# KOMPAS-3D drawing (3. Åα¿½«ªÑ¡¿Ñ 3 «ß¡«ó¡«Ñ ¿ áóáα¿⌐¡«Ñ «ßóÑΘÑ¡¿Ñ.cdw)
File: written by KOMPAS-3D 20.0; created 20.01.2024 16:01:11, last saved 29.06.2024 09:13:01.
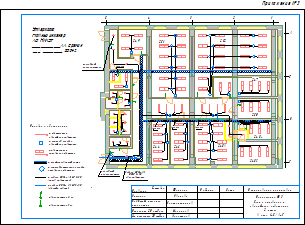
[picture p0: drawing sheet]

Sheet 1: A4, landscape

Document properties: Автор: Пользователь Windows; Организация: НИИЭТ; Полное имя файла: \\Storage\20 Отдел\Мои документы\Крашенинников Е\ТЗ 2й этаж\готово\3. Приложение 3 основное и аварийное освещение.cdw

Title block, sheet 1: scale: 1:1; Количество листов документа: 1; Форматы листов документа: A4

Views: Вид 1, Вид 2
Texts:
  Приложение №3
  Кабель ВВГнг(А)
  FRLS 3х1,5
  авар.освещения
  проходной
  переключатель
  - светильники
  аварийного освещения
  - распред. коробка
  основного освещения
  - перфорированный лоток
  - распределительные коробки
  - кабель ВВГнг (А) LS 3х1,5
  (аварийн. освещ..)
  (основ. освещения)
  - выключатель 2 кл.
  - выключатель 1 кл.
  Утверждаю
  Главный инженер
  АО "НИИЭТ"
  Составил
  Фамилия
  Подпись
  Дата
  Наименование планировки
  Инженер
  Иванова
  Схема основного и
  в осях 1-5/А-Г.
  Ведущий инженер
  энергетик
  Крашенинников
  Начальник 20 отдела
  Меренков
  Зам. начальника 20 отдела
  Хорошилов
  Условные обозначения
  выкл 1кл
  выкл 2кл
  200_ШТРИХ_RGB_255_0_0_SC_1_THICK_0.09
  FP_1_ISO 8
  FP_1_ISO 7
  FP_1_ISO 6
  FP_1_ISO 5
  FP_1_ISO 4
  FP_1_ISO 3
  FP_1_ISO 2
  FP_1_ISO 1
  FP_1_ISO 0
  FP_3_ISO 83
  FP_3_ISO 82
  FP_3_ISO 81
  FP_3_ISO 80
  FP_3_ISO 79
  FP_3_ISO 78
  FP_3_ISO 77
  FP_3_ISO 76
  FP_3_ISO 75
  FP_3_ISO 74
  FP_3_ISO 73
  FP_3_ISO 72
  FP_3_ISO 71
  FP_3_ISO 70
  FP_3_ISO 69
  FP_3_ISO 68
  FP_3_ISO 67
  FP_3_ISO 66
  FP_3_ISO 65
  FP_3_ISO 64
  FP_3_ISO 63
  FP_3_ISO 62
  FP_3_ISO 61
  FP_3_ISO 60
  FP_3_ISO 59
  FP_3_ISO 58
  FP_3_ISO 57
  FP_3_ISO 56
  FP_3_ISO 55
  FP_3_ISO 54
  FP_3_ISO 53
  FP_3_ISO 52
  FP_3_ISO 51
  FP_3_ISO 50
  FP_3_ISO 49
  FP_3_ISO 48
  FP_3_ISO 47
  FP_3_ISO 46
  FP_3_ISO 45
  FP_3_ISO 44
  FP_3_ISO 43
  FP_3_ISO 42
  FP_3_ISO 41
  FP_3_ISO 40
  FP_3_ISO 39
  FP_3_ISO 38
  FP_3_ISO 37
  FP_3_ISO 36
  FP_3_ISO 35
  FP_3_ISO 34
  FP_3_ISO 33
  FP_3_ISO 32
  FP_3_ISO 31
  FP_3_ISO 30
  FP_3_ISO 29
  FP_3_ISO 28
  FP_3_ISO 27
  FP_3_ISO 26
  FP_3_ISO 25
  FP_3_ISO 24
  FP_3_ISO 23
  FP_3_ISO 22
  FP_3_ISO 21
  FP_3_ISO 20
  FP_3_ISO 19
  FP_3_ISO 18
  FP_3_ISO 17
  FP_3_ISO 16
  FP_3_ISO 15
  FP_3_ISO 14
  FP_3_ISO 13
  FP_3_ISO 12
  FP_5_ISO 83
  FP_5_ISO 82
  FP_5_ISO 81
  FP_5_ISO 80
  FP_5_ISO 79
  FP_5_ISO 78
  FP_5_ISO 77
  FP_5_ISO 76
  FP_5_ISO 75
  FP_5_ISO 74
  FP_5_ISO 73
  FP_5_ISO 72
  FP_5_ISO 71
  FP_5_ISO 70
  FP_5_ISO 69
  FP_5_ISO 68
  FP_5_ISO 67
  FP_5_ISO 66
  FP_5_ISO 65
  FP_5_ISO 64
  FP_5_ISO 63
  FP_5_ISO 62
  FP_5_ISO 61
  FP_5_ISO 60
  FP_5_ISO 59
  FP_5_ISO 58
  FP_5_ISO 57
  FP_5_ISO 56
  FP_5_ISO 55
  FP_5_ISO 54
  FP_5_ISO 53
  FP_5_ISO 52
  FP_5_ISO 51
  FP_5_ISO 50
  FP_5_ISO 49
  FP_5_ISO 48
  FP_5_ISO 47
  FP_5_ISO 46
  FP_5_ISO 45
  FP_5_ISO 44
  FP_5_ISO 43
  FP_5_ISO 42
  FP_5_ISO 41
  FP_5_ISO 40
  FP_5_ISO 39
  FP_5_ISO 38
  FP_5_ISO 37
  FP_5_ISO 36
  FP_5_ISO 35
  FP_5_ISO 34
  FP_5_ISO 33
  FP_5_ISO 32
  FP_5_ISO 31
  FP_5_ISO 30
  FP_5_ISO 29
  FP_5_ISO 28
  FP_5_ISO 27
  FP_5_ISO 26
  FP_5_ISO 25
  FP_5_ISO 24
  FP_5_ISO 23
  FP_5_ISO 22
  FP_5_ISO 21
  FP_5_ISO 20
  FP_5_ISO 19
  FP_5_ISO 18
  FP_5_ISO 17
  FP_5_ISO 16
  FP_5_ISO 15
  FP_5_ISO 14
  FP_5_ISO 13
  FP_5_ISO 12
  FP3_1_ISO 0
  FP3_1_ISO 1
  FP3_1_ISO 2
  FP3_1_ISO 3
  FP3_1_ISO 4
  FP3_1_ISO 5
  FP3_1_ISO 6
  FP3_1_ISO 7
  FP3_1_ISO 8
  FP3_1_ISO 9
  FP3_1_ISO 10
  FP3_1_ISO 11
  FP3_1_ISO 12
  FP3_1_ISO 13
  FP3_1_ISO 14
  FP3_1_ISO 15
  FP3_2_ISO 0
  FP3_2_ISO 1
  FP3_2_ISO 2
  FP3_2_ISO 3
  FP3_2_ISO 4
  FP3_2_ISO 5
  FP3_2_ISO 6
  FP3_2_ISO 7
  FP3_2_ISO 8
  FP3_2_ISO 9
  FP3_2_ISO 10
  FP3_2_ISO 11
  FP3_2_ISO 12
  FP3_2_ISO 13
  FP3_2_ISO 14
  FP3_2_ISO 15
  FP3_3_ISO 0
  FP3_3_ISO 1
  FP3_3_ISO 2
  FP3_3_ISO 3
  FP3_3_ISO 4
  FP3_3_ISO 5
  FP3_3_ISO 6
  FP3_3_ISO 7
  FP3_3_ISO 8
  FP3_3_ISO 9
  FP3_3_ISO 10
  FP3_3_ISO 11
  FP3_3_ISO 12
  FP3_3_ISO 13
  FP3_3_ISO 14
  FP3_3_ISO 15
  FP3_4_ISO 0
  FP3_4_ISO 1
  FP3_4_ISO 2
  FP3_4_ISO 3
  FP3_4_ISO 4
  FP3_4_ISO 5
  FP3_4_ISO 6
  FP3_4_ISO 7
  FP3_4_ISO 8
  FP3_4_ISO 9
  FP3_4_ISO 10
  FP3_4_ISO 11
  FP3_4_ISO 12
  FP3_4_ISO 13
  FP3_4_ISO 14
  FP3_4_ISO 15
  FP3_5_ISO 0
  FP3_5_ISO 1
  FP3_5_ISO 2
  FP3_5_ISO 3
  FP3_5_ISO 4
  FP3_5_ISO 5
  FP3_5_ISO 6
  FP3_5_ISO 7
  FP3_5_ISO 8
  FP3_5_ISO 9
  FP3_5_ISO 10
  FP3_5_ISO 11
  FP3_5_ISO 12
  FP3_5_ISO 13
  FP3_5_ISO 14
  FP3_5_ISO 15
  FP3_6_ISO 0
  FP3_6_ISO 1
  FP3_6_ISO 2
  FP3_6_ISO 3
  FP3_6_ISO 4
  FP3_6_ISO 5
  FP3_6_ISO 6
  FP3_6_ISO 7
  FP3_6_ISO 8
  FP3_6_ISO 9
  FP3_6_ISO 10
  FP3_6_ISO 11
  FP3_6_ISO 12
  FP3_6_ISO 13
  FP3_6_ISO 14
  FP3_6_ISO 15
  FP3_7_ISO 0
  FP3_7_ISO 1
  FP3_7_ISO 2
  FP3_7_ISO 3
  FP3_7_ISO 4
  FP3_7_ISO 5
  FP3_7_ISO 6
  FP3_7_ISO 7
  FP3_7_ISO 8
  FP3_7_ISO 9
  FP3_7_ISO 10
  FP3_7_ISO 11
  FP3_7_ISO 12
  FP3_7_ISO 13
  FP3_7_ISO 14
  FP3_7_ISO 15
  FP3_8_ISO 0
  FP3_8_ISO 1
  FP3_8_ISO 2
  FP3_8_ISO 3
  FP3_8_ISO 4
  FP3_8_ISO 5
  FP3_8_ISO 6
  FP3_8_ISO 7
  FP3_8_ISO 8
  FP3_8_ISO 9
  FP3_8_ISO 10
  FP3_8_ISO 11
  FP3_8_ISO 12
  FP3_8_ISO 13
  FP3_8_ISO 14
  FP3_8_ISO 15
  FP3_9_ISO 0
  FP3_9_ISO 1
  FP3_9_ISO 2
  FP3_9_ISO 3
  FP3_9_ISO 4
  FP3_9_ISO 5
  FP3_9_ISO 6
  FP3_9_ISO 7
  FP3_9_ISO 8
  FP3_9_ISO 9
  FP3_9_ISO 10
  FP3_9_ISO 11
  FP3_9_ISO 12
  FP3_9_ISO 13
  FP3_9_ISO 14
  FP3_9_ISO 15
  FP3_10_ISO 0
  FP3_10_ISO 1
  FP3_10_ISO 2
  FP3_10_ISO 3
  FP3_10_ISO 4
  FP3_10_ISO 5
  FP3_10_ISO 6
  FP3_10_ISO 7
  FP3_10_ISO 8
  FP3_10_ISO 9
  FP3_10_ISO 10
  FP3_10_ISO 11
  FP3_10_ISO 12
  FP3_10_ISO 13
  FP3_10_ISO 14
  FP3_10_ISO 15
  FP3_11_ISO 0
  FP3_11_ISO 1
  FP3_11_ISO 2
  FP3_11_ISO 3
  FP3_11_ISO 4
  FP3_11_ISO 5
  FP3_11_ISO 6
  FP3_11_ISO 7
  FP3_11_ISO 8
  FP3_11_ISO 9
  FP3_11_ISO 10
  FP3_11_ISO 11
  FP3_11_ISO 12
  FP3_11_ISO 13
  FP3_11_ISO 14
  FP3_11_ISO 15
  FP3_13_ISO 0
  FP3_13_ISO 1
  FP3_13_ISO 2
  FP3_13_ISO 3
  FP3_13_ISO 4
  FP3_13_ISO 5
  FP3_13_ISO 6
  FP3_13_ISO 7
  FP3_13_ISO 8
  FP3_13_ISO 9
  FP3_13_ISO 10
  FP3_13_ISO 11
  FP3_13_ISO 12
  FP3_13_ISO 13
  FP3_13_ISO 14
  FP3_13_ISO 15
  FP3_14_ISO 0
  FP3_14_ISO 1
  FP3_14_ISO 2
  FP3_14_ISO 3
  FP3_14_ISO 4
  FP3_14_ISO 5
  FP3_14_ISO 6
  FP3_14_ISO 7
  FP3_14_ISO 8
  FP3_14_ISO 9
  FP3_14_ISO 10
  FP3_14_ISO 11
  FP3_14_ISO 12
  FP3_14_ISO 13
  FP3_14_ISO 14
  FP3_14_ISO 15
  FP3_15_ISO 0
  FP3_15_ISO 1
  FP3_15_ISO 2
  FP3_15_ISO 3
  FP3_15_ISO 4
  FP3_15_ISO 5
  FP3_15_ISO 6
  FP3_15_ISO 7
  FP3_15_ISO 8
  FP3_15_ISO 9
  FP3_15_ISO 10
  FP3_15_ISO 11
  FP3_15_ISO 12
  FP3_15_ISO 13
  FP3_15_ISO 14
  FP3_15_ISO 15
  FP3_16_ISO 0
  FP3_16_ISO 1
  FP3_16_ISO 2
  FP3_16_ISO 3
  FP3_16_ISO 4
  FP3_16_ISO 5
  FP3_16_ISO 6
  FP3_16_ISO 7
  FP3_16_ISO 8
  FP3_16_ISO 9
  FP3_16_ISO 10
  FP3_16_ISO 11
  FP3_16_ISO 12
  FP3_16_ISO 13
  FP3_16_ISO 14
  FP3_16_ISO 15
  FP3_17_ISO 0
  FP3_17_ISO 1
  FP3_17_ISO 2
  FP3_17_ISO 3
  FP3_17_ISO 4
  FP3_17_ISO 5
  FP3_17_ISO 6
  FP3_17_ISO 7
  FP3_17_ISO 8
  FP3_17_ISO 9
  FP3_17_ISO 10
  FP3_17_ISO 11
  FP3_17_ISO 12
  FP3_17_ISO 13
  FP3_17_ISO 14
  FP3_17_ISO 15
  FP3_19_ISO 0
  FP3_19_ISO 1
  FP3_19_ISO 2
  FP3_19_ISO 3
  FP3_19_ISO 4
  FP3_19_ISO 5
  FP3_19_ISO 6
  FP3_19_ISO 7
  FP3_19_ISO 8
  FP3_19_ISO 9
  FP3_19_ISO 10
  FP3_19_ISO 11
  FP3_19_ISO 12
  FP3_19_ISO 13
  FP3_19_ISO 14
  FP3_19_ISO 15
  FP3_20_ISO 0
  FP3_20_ISO 1
  FP3_20_ISO 2
  FP3_20_ISO 3
  FP3_20_ISO 4
  FP3_20_ISO 5
  FP3_20_ISO 6
  FP3_20_ISO 7
  FP3_20_ISO 8
  FP3_20_ISO 9
  FP3_20_ISO 10
  FP3_20_ISO 11
  FP3_20_ISO 12
  FP3_20_ISO 13
  FP3_20_ISO 14
  FP3_20_ISO 15
  FP3_21_ISO 0
  FP3_21_ISO 1
  FP3_21_ISO 2
  FP3_21_ISO 3
  FP3_21_ISO 4
  FP3_21_ISO 5
  FP3_21_ISO 6
  FP3_21_ISO 7
  FP3_21_ISO 8
  FP3_21_ISO 9
  FP3_21_ISO 10
  FP3_21_ISO 11
  FP3_21_ISO 12
  FP3_21_ISO 13
  FP3_21_ISO 14
  FP3_21_ISO 15
  FP3_22_ISO 0
  FP3_22_ISO 1
  FP3_22_ISO 2
  FP3_22_ISO 3
  FP3_22_ISO 4
  FP3_22_ISO 5
  FP3_22_ISO 6
  FP3_22_ISO 7
  FP3_22_ISO 8
  FP3_22_ISO 9
  FP3_22_ISO 10
  FP3_22_ISO 11
  FP3_22_ISO 12
  FP3_22_ISO 13
  FP3_22_ISO 14
  FP3_22_ISO 15
  FP3_23_ISO 0
  FP3_23_ISO 1
  FP3_23_ISO 2
  FP3_23_ISO 3
  FP3_23_ISO 4
  FP3_23_ISO 5
  FP3_23_ISO 6
  FP3_23_ISO 7
  FP3_23_ISO 8
  FP3_23_ISO 9
  FP3_23_ISO 10
  FP3_23_ISO 11
  FP3_23_ISO 12
  FP3_23_ISO 13
  FP3_23_ISO 14
  FP3_23_ISO 15
  FP3_24_ISO 0
  FP3_24_ISO 1
  FP3_24_ISO 2
  FP3_24_ISO 3
  FP3_24_ISO 4
  FP3_24_ISO 5
  FP3_24_ISO 6
  FP3_24_ISO 7
  FP3_24_ISO 8
  FP3_24_ISO 9
  FP3_24_ISO 10
  FP3_24_ISO 11
  FP3_24_ISO 12
  FP3_24_ISO 13
  FP3_24_ISO 14
  FP3_24_ISO 15
  FP3_25_ISO 0
  FP3_25_ISO 1
  FP3_25_ISO 2
  FP3_25_ISO 3
  FP3_25_ISO 4
  FP3_25_ISO 5
  FP3_25_ISO 6
  FP3_25_ISO 7
  FP3_25_ISO 8
  FP3_25_ISO 9
  FP3_25_ISO 10
  FP3_25_ISO 11
  FP3_25_ISO 12
  FP3_25_ISO 13
  FP3_25_ISO 14
  FP3_25_ISO 15
  FP3_26_ISO 0
  FP3_26_ISO 1
  FP3_26_ISO 2
  FP3_26_ISO 3
  FP3_26_ISO 4
  FP3_26_ISO 5
  FP3_26_ISO 6
  FP3_26_ISO 7
  FP3_26_ISO 8
  FP3_26_ISO 9
  FP3_26_ISO 10
  FP3_26_ISO 11
  FP3_26_ISO 12
  FP3_26_ISO 13
  FP3_26_ISO 14
  FP3_26_ISO 15
  FP3_28_ISO 0
  FP3_28_ISO 1
  FP3_28_ISO 2
  FP3_28_ISO 3
  FP3_28_ISO 4
  FP3_28_ISO 5
  FP3_28_ISO 6
  FP3_28_ISO 7
  FP3_28_ISO 8
  FP3_28_ISO 9
  FP3_28_ISO 10
  FP3_28_ISO 11
  FP3_28_ISO 12
  FP3_28_ISO 13
  FP3_28_ISO 14
  FP3_28_ISO 15
  FP3_29_ISO 0
  FP3_29_ISO 1
  FP3_29_ISO 2
  FP3_29_ISO 3
  FP3_29_ISO 4
  FP3_29_ISO 5
  FP3_29_ISO 6
  FP3_29_ISO 7
  FP3_29_ISO 8
  FP3_29_ISO 9
  FP3_29_ISO 10
  FP3_29_ISO 11
  FP3_29_ISO 12
  FP3_29_ISO 13
  FP3_29_ISO 14
  FP3_29_ISO 15
  FP3_31_ISO 0
  FP3_31_ISO 1
  FP3_31_ISO 2
  FP3_31_ISO 3
  FP3_31_ISO 4
  FP3_31_ISO 5
  FP3_31_ISO 6
  FP3_31_ISO 7
  FP3_31_ISO 8
  FP3_31_ISO 9
  FP3_31_ISO 10
  FP3_31_ISO 11
  FP3_31_ISO 12
  FP3_31_ISO 13
  FP3_31_ISO 14
  FP3_31_ISO 15
  FP3_32_ISO 0
  FP3_32_ISO 1
  FP3_32_ISO 2
  FP3_32_ISO 3
  FP3_32_ISO 4
  FP3_32_ISO 5
  FP3_32_ISO 6
  FP3_32_ISO 7
  FP3_32_ISO 8
  FP3_32_ISO 9
  FP3_32_ISO 10
  FP3_32_ISO 11
  FP3_32_ISO 12
  FP3_32_ISO 13
  FP3_32_ISO 14
  FP3_32_ISO 15
  FP3_33_ISO 0
  FP3_33_ISO 1
  FP3_33_ISO 2
  FP3_33_ISO 3
  FP3_33_ISO 4
  FP3_33_ISO 5
  FP3_33_ISO 6
  FP3_33_ISO 7
  FP3_33_ISO 8
  FP3_33_ISO 9
  FP3_33_ISO 10
  FP3_33_ISO 11
  FP3_33_ISO 12
  FP3_33_ISO 13
  FP3_33_ISO 14
  FP3_33_ISO 15
  FP3_35_ISO 0
  FP3_35_ISO 1
  FP3_35_ISO 2
  FP3_35_ISO 3
  FP3_35_ISO 4
  FP3_35_ISO 5
  FP3_35_ISO 6
  FP3_35_ISO 7
  FP3_35_ISO 8
  FP3_35_ISO 9
  FP3_35_ISO 10
  FP3_35_ISO 11
  FP3_35_ISO 12
  FP3_35_ISO 13
  FP3_35_ISO 14
  FP3_35_ISO 15
  FP3_36_ISO 0
  FP3_36_ISO 1
  FP3_36_ISO 2
  FP3_36_ISO 3
  FP3_36_ISO 4
  FP3_36_ISO 5
  FP3_36_ISO 6
  FP3_36_ISO 7
  FP3_36_ISO 8
  FP3_36_ISO 9
  FP3_36_ISO 10
  FP3_36_ISO 11
  FP3_36_ISO 12
  FP3_36_ISO 13
  FP3_36_ISO 14
  FP3_36_ISO 15
  FP3_37_ISO 0
  FP3_37_ISO 1
  FP3_37_ISO 2
  FP3_37_ISO 3
  FP3_37_ISO 4
  FP3_37_ISO 5
  FP3_37_ISO 6
  FP3_37_ISO 7
  FP3_37_ISO 8
  FP3_37_ISO 9
  FP3_37_ISO 10
  FP3_37_ISO 11
  FP3_37_ISO 12
  FP3_37_ISO 13
  FP3_37_ISO 14
  FP3_37_ISO 15
  FP3_38_ISO 0
  FP3_38_ISO 1
  FP3_38_ISO 2
  FP3_38_ISO 3
  FP3_38_ISO 4
  FP3_38_ISO 5
  FP3_38_ISO 6
  FP3_38_ISO 7
  FP3_38_ISO 8
  FP3_38_ISO 9
  FP3_38_ISO 10
  FP3_38_ISO 11
  FP3_38_ISO 12
  FP3_38_ISO 13
  FP3_38_ISO 14
  FP3_38_ISO 15
  FP3_39_ISO 0
  FP3_39_ISO 1
  FP3_39_ISO 2
  FP3_39_ISO 3
  FP3_39_ISO 4
  FP3_39_ISO 5
  FP3_39_ISO 6
  FP3_39_ISO 7
  FP3_39_ISO 8
  FP3_39_ISO 9
  FP3_39_ISO 10
  FP3_39_ISO 11
  FP3_39_ISO 12
  FP3_39_ISO 13
  FP3_39_ISO 14
  FP3_39_ISO 15
  FP3_40_ISO 0
  FP3_40_ISO 1
  FP3_40_ISO 2
  FP3_40_ISO 3
  FP3_40_ISO 4
  FP3_40_ISO 5
  FP3_40_ISO 6
  FP3_40_ISO 7
  FP3_40_ISO 8
  FP3_40_ISO 9
  FP3_40_ISO 10
  FP3_40_ISO 11
  FP3_40_ISO 12
  FP3_40_ISO 13
  FP3_40_ISO 14
  FP3_40_ISO 15
  FP3_41_ISO 0
  FP3_41_ISO 1
  FP3_41_ISO 2
  FP3_41_ISO 3
  FP3_41_ISO 4
  FP3_41_ISO 5
  FP3_41_ISO 6
  FP3_41_ISO 7
  FP3_41_ISO 8
  FP3_41_ISO 9
  FP3_41_ISO 10
  FP3_41_ISO 11
  FP3_41_ISO 12
  FP3_41_ISO 13
  FP3_41_ISO 14
  FP3_41_ISO 15
  FP3_42_ISO 0
  FP3_42_ISO 1
  FP3_42_ISO 2
  FP3_42_ISO 3
  FP3_42_ISO 4
  FP3_42_ISO 5
  FP3_42_ISO 6
  FP3_42_ISO 7
  FP3_42_ISO 8
  FP3_42_ISO 9
  FP3_42_ISO 10
  FP3_42_ISO 11
  FP3_42_ISO 12
  FP3_42_ISO 13
  FP3_42_ISO 14
  FP3_42_ISO 15
  FP3_44_ISO 0
  FP3_44_ISO 1
  FP3_44_ISO 2
  FP3_44_ISO 3
  FP3_44_ISO 4
  FP3_44_ISO 5
  FP3_44_ISO 6
  FP3_44_ISO 7
  FP3_44_ISO 8
  FP3_44_ISO 9
  FP3_44_ISO 10
  FP3_44_ISO 11
  FP3_44_ISO 12
  FP3_44_ISO 13
  FP3_44_ISO 14
  FP3_44_ISO 15
  FP3_45_ISO 0
  FP3_45_ISO 1
  FP3_45_ISO 2
  FP3_45_ISO 3
  FP3_45_ISO 4
  FP3_45_ISO 5
  FP3_45_ISO 6
  FP3_45_ISO 7
  FP3_45_ISO 8
  FP3_45_ISO 9
  FP3_45_ISO 10
  FP3_45_ISO 11
  FP3_45_ISO 12
  FP3_45_ISO 13
  FP3_45_ISO 14
  FP3_45_ISO 15
  FP3_46_ISO 0
  FP3_46_ISO 1
  FP3_46_ISO 2
  FP3_46_ISO 3
  FP3_46_ISO 4
  FP3_46_ISO 5
  FP3_46_ISO 6
  FP3_46_ISO 7
  FP3_46_ISO 8
  FP3_46_ISO 9
  FP3_46_ISO 10
  FP3_46_ISO 11
  FP3_46_ISO 12
  FP3_46_ISO 13
  FP3_46_ISO 14
  FP3_46_ISO 15
  FP3_47_ISO 0
  FP3_47_ISO 1
  FP3_47_ISO 2
  FP3_47_ISO 3
  FP3_47_ISO 4
  FP3_47_ISO 5
  FP3_47_ISO 6
  FP3_47_ISO 7
  FP3_47_ISO 8
  FP3_47_ISO 9
  FP3_47_ISO 10
  FP3_47_ISO 11
  FP3_47_ISO 12
  FP3_47_ISO 13
  FP3_47_ISO 14
  FP3_47_ISO 15
  FP3_48_ISO 0
  FP3_48_ISO 1
  FP3_48_ISO 2
  FP3_48_ISO 3
  FP3_48_ISO 4
  FP3_48_ISO 5
  FP3_48_ISO 6
  FP3_48_ISO 7
  FP3_48_ISO 8
  FP3_48_ISO 9
  FP3_48_ISO 10
  FP3_48_ISO 11
  FP3_48_ISO 12
  FP3_48_ISO 13
  FP3_48_ISO 14
  FP3_48_ISO 15
  FP3_49_ISO 0
  FP3_49_ISO 1
  FP3_49_ISO 2
  FP3_49_ISO 3
  FP3_49_ISO 4
  FP3_49_ISO 5
  FP3_49_ISO 6
  FP3_49_ISO 7
  FP3_49_ISO 8
  FP3_49_ISO 9
  FP3_49_ISO 10
  FP3_49_ISO 11
  FP3_49_ISO 12
  FP3_49_ISO 13
  FP3_49_ISO 14
  FP3_49_ISO 15
  FP3_50_ISO 0
  FP3_50_ISO 1
  FP3_50_ISO 2
  FP3_50_ISO 3
  FP3_50_ISO 4
  FP3_50_ISO 5
  FP3_50_ISO 6
  FP3_50_ISO 7
  FP3_50_ISO 8
  FP3_50_ISO 9
  FP3_50_ISO 10
  FP3_50_ISO 11
  FP3_50_ISO 12
  FP3_50_ISO 13
  FP3_50_ISO 14
  FP3_50_ISO 15
  FP3_51_ISO 0
  FP3_51_ISO 1
  FP3_51_ISO 2
  FP3_51_ISO 3
  FP3_51_ISO 4
  FP3_51_ISO 5
  FP3_51_ISO 6
  FP3_51_ISO 7
  FP3_51_ISO 8
  FP3_51_ISO 9
  FP3_51_ISO 10
  FP3_51_ISO 11
  FP3_51_ISO 12
  FP3_51_ISO 13
  FP3_51_ISO 14
  FP3_51_ISO 15
  FP3_52_ISO 0
  FP3_52_ISO 1
  FP3_52_ISO 2
  FP3_52_ISO 3
  FP3_52_ISO 4
  FP3_52_ISO 5
  FP3_52_ISO 6
  FP3_52_ISO 7
  FP3_52_ISO 8
  FP3_52_ISO 9
  FP3_52_ISO 10
  FP3_52_ISO 11
  FP3_52_ISO 12
  FP3_52_ISO 13
  FP3_52_ISO 14
  FP3_52_ISO 15
  FP3_53_ISO 0
  FP3_53_ISO 1
  FP3_53_ISO 2
  FP3_53_ISO 3
  FP3_53_ISO 4
  FP3_53_ISO 5
  FP3_53_ISO 6
  FP3_53_ISO 7
  FP3_53_ISO 8
  FP3_53_ISO 9
  FP3_53_ISO 10
  FP3_53_ISO 11
  FP3_53_ISO 12
  FP3_53_ISO 13
  FP3_53_ISO 14
  FP3_53_ISO 15
  FP3_54_ISO 0
  FP3_54_ISO 1
  FP3_54_ISO 2
  FP3_54_ISO 3
  FP3_54_ISO 4
  FP3_54_ISO 5
  FP3_54_ISO 6
  FP3_54_ISO 7
  FP3_54_ISO 8
  FP3_54_ISO 9
  FP3_54_ISO 10
  FP3_54_ISO 11
  FP3_54_ISO 12
  FP3_54_ISO 13
  FP3_54_ISO 14
  FP3_54_ISO 15
  FP3_55_ISO 0
  FP3_55_ISO 1
  FP3_55_ISO 2
  FP3_55_ISO 3
  FP3_55_ISO 4
  FP3_55_ISO 5
  FP3_55_ISO 6
  FP3_55_ISO 7
  FP3_55_ISO 8
  FP3_55_ISO 9
  FP3_55_ISO 10
  FP3_55_ISO 11
  FP3_55_ISO 12
  FP3_55_ISO 13
  FP3_55_ISO 14
  FP3_55_ISO 15
  FP3_56_ISO 0
  FP3_56_ISO 1
  FP3_56_ISO 2
  FP3_56_ISO 3
  FP3_56_ISO 4
  FP3_56_ISO 5
  FP3_56_ISO 6
  FP3_56_ISO 7
  FP3_56_ISO 8
  FP3_56_ISO 9
  FP3_56_ISO 10
  FP3_56_ISO 11
  FP3_56_ISO 12
  FP3_56_ISO 13
  FP3_56_ISO 14
  FP3_56_ISO 15
  FP3_57_ISO 0
  FP3_57_ISO 1
  FP3_57_ISO 2
  FP3_57_ISO 3
  FP3_57_ISO 4
  FP3_57_ISO 5
  FP3_57_ISO 6
  FP3_57_ISO 7
  FP3_57_ISO 8
  FP3_57_ISO 9
  FP3_57_ISO 10
  FP3_57_ISO 11
  FP3_57_ISO 12
  FP3_57_ISO 13
  FP3_57_ISO 14
  FP3_57_ISO 15
  FP3_58_ISO 0
  FP3_58_ISO 1
  FP3_58_ISO 2
  FP3_58_ISO 3
  FP3_58_ISO 4
  FP3_58_ISO 5
  FP3_58_ISO 6
  FP3_58_ISO 7
  FP3_58_ISO 8
  FP3_58_ISO 9
  FP3_58_ISO 10
  FP3_58_ISO 11
  FP3_58_ISO 12
  FP3_58_ISO 13
  FP3_58_ISO 14
  FP3_58_ISO 15
  FP3_59_ISO 0
  FP3_59_ISO 1
  FP3_59_ISO 2
  FP3_59_ISO 3
  FP3_59_ISO 4
  FP3_59_ISO 5
  FP3_59_ISO 6
  FP3_59_ISO 7
  FP3_59_ISO 8
  FP3_59_ISO 9
  FP3_59_ISO 10
  FP3_59_ISO 11
  FP3_59_ISO 12
  FP3_59_ISO 13
  FP3_59_ISO 14
  FP3_59_ISO 15
  FP3_60_ISO 0
  FP3_60_ISO 1
  FP3_60_ISO 2
  FP3_60_ISO 3
  FP3_60_ISO 4
  FP3_60_ISO 5
  FP3_60_ISO 6
  FP3_60_ISO 7
  FP3_60_ISO 8
  FP3_60_ISO 9
  FP3_60_ISO 10
  FP3_60_ISO 11
  FP3_60_ISO 12
  FP3_60_ISO 13
  FP3_60_ISO 14
  FP3_60_ISO 15
  FP3_61_ISO 0
  FP3_61_ISO 1
  FP3_61_ISO 2
  FP3_61_ISO 3
  FP3_61_ISO 4
  FP3_61_ISO 5
  FP3_61_ISO 6
  FP3_61_ISO 7
  FP3_61_ISO 8
  FP3_61_ISO 9
  FP3_61_ISO 10
  FP3_61_ISO 11
  FP3_61_ISO 12
  FP3_61_ISO 13
  FP3_61_ISO 14
  FP3_61_ISO 15
  FP3_62_ISO 0
  FP3_62_ISO 1
  FP3_62_ISO 2
  FP3_62_ISO 3
  FP3_62_ISO 4
  FP3_62_ISO 5
  FP3_62_ISO 6
  FP3_62_ISO 7
  FP3_62_ISO 8
  FP3_62_ISO 9
  FP3_62_ISO 10
  FP3_62_ISO 11
  FP3_62_ISO 12
  FP3_62_ISO 13
  FP3_62_ISO 14
  FP3_62_ISO 15
  FP3_63_ISO 0
  FP3_63_ISO 1
  FP3_63_ISO 2
  FP3_63_ISO 3
  FP3_63_ISO 4
  FP3_63_ISO 5
  FP3_63_ISO 6
  FP3_63_ISO 7
  FP3_63_ISO 8
  FP3_63_ISO 9
  FP3_63_ISO 10
  FP3_63_ISO 11
  FP3_63_ISO 12
  FP3_63_ISO 13
  FP3_63_ISO 14
  FP3_63_ISO 15
  FP3_64_ISO 0
  FP3_64_ISO 1
  FP3_64_ISO 2
  FP3_64_ISO 3
  FP3_64_ISO 4
  FP3_64_ISO 5
  FP3_64_ISO 6
  FP3_64_ISO 7
  FP3_64_ISO 8
  FP3_64_ISO 9
  FP3_64_ISO 10
  FP3_64_ISO 11
  FP3_64_ISO 12
  FP3_64_ISO 13
  FP3_64_ISO 14
  FP3_64_ISO 15
  FP3_65_ISO 0
  FP3_65_ISO 1
  FP3_65_ISO 2
  FP3_65_ISO 3
  FP3_65_ISO 4
  FP3_65_ISO 5
  FP3_65_ISO 6
  FP3_65_ISO 7
  FP3_65_ISO 8
  FP3_65_ISO 9
  FP3_65_ISO 10
  FP3_65_ISO 11
  FP3_65_ISO 12
  FP3_65_ISO 13
  FP3_65_ISO 14
  FP3_65_ISO 15
  FP3_66_ISO 0
  FP3_66_ISO 1
  FP3_66_ISO 2
  FP3_66_ISO 3
  FP3_66_ISO 4
  FP3_66_ISO 5
  FP3_66_ISO 6
  FP3_66_ISO 7
  FP3_66_ISO 8
  FP3_66_ISO 9
  FP3_66_ISO 10
  FP3_66_ISO 11
  FP3_66_ISO 12
  FP3_66_ISO 13
  FP3_66_ISO 14
  FP3_66_ISO 15
  FP3_67_ISO 0
  FP3_67_ISO 1
  FP3_67_ISO 2
  FP3_67_ISO 3
  FP3_67_ISO 4
  FP3_67_ISO 5
  FP3_67_ISO 6
  FP3_67_ISO 7
  FP3_67_ISO 8
  FP3_67_ISO 9
  FP3_67_ISO 10
  FP3_67_ISO 11
  FP3_67_ISO 12
  FP3_67_ISO 13
  FP3_67_ISO 14
  FP3_67_ISO 15
  FP3_68_ISO 0
  FP3_68_ISO 1
  FP3_68_ISO 2
  FP3_68_ISO 3
  FP3_68_ISO 4
  FP3_68_ISO 5
  FP3_68_ISO 6
  FP3_68_ISO 7
  FP3_68_ISO 8
  FP3_68_ISO 9
  FP3_68_ISO 10
  FP3_68_ISO 11
  FP3_68_ISO 12
  FP3_68_ISO 13
  FP3_68_ISO 14
  FP3_68_ISO 15
  FP3_69_ISO 0
  FP3_69_ISO 1
  FP3_69_ISO 2
  FP3_69_ISO 3
  FP3_69_ISO 4
  FP3_69_ISO 5
  FP3_69_ISO 6
  FP3_69_ISO 7
  FP3_69_ISO 8
  FP3_69_ISO 9
  FP3_69_ISO 10
  FP3_69_ISO 11
  FP3_69_ISO 12
  FP3_69_ISO 13
  FP3_69_ISO 14
  FP3_69_ISO 15
  FP3_71_ISO 0
  FP3_71_ISO 1
  FP3_71_ISO 2
  FP3_71_ISO 3
  FP3_71_ISO 4
  FP3_71_ISO 5
  FP3_71_ISO 6
  FP3_71_ISO 7
  FP3_71_ISO 8
  FP3_71_ISO 9
  FP3_71_ISO 10
  FP3_71_ISO 11
  FP3_71_ISO 12
  FP3_71_ISO 13
  FP3_71_ISO 14
  FP3_71_ISO 15
  FP3_72_ISO 0
  FP3_72_ISO 1
  FP3_72_ISO 2
  FP3_72_ISO 3
  FP3_72_ISO 4
  FP3_72_ISO 5
  FP3_72_ISO 6
  FP3_72_ISO 7
  FP3_72_ISO 8
  FP3_72_ISO 9
  FP3_72_ISO 10
  FP3_72_ISO 11
  FP3_72_ISO 12
  FP3_72_ISO 13
  FP3_72_ISO 14
  FP3_72_ISO 15
  FP3_73_ISO 0
  FP3_73_ISO 1
  FP3_73_ISO 2
  FP3_73_ISO 3
  FP3_73_ISO 4
  FP3_73_ISO 5
  FP3_73_ISO 6
  FP3_73_ISO 7
  FP3_73_ISO 8
  FP3_73_ISO 9
  FP3_73_ISO 10
  FP3_73_ISO 11
  FP3_73_ISO 12
  FP3_73_ISO 13
  FP3_73_ISO 14
  FP3_73_ISO 15
  FP3_74_ISO 0
  FP3_74_ISO 1
  FP3_74_ISO 2
  FP3_74_ISO 3
  FP3_74_ISO 4
  FP3_74_ISO 5
  FP3_74_ISO 6
  FP3_74_ISO 7
  FP3_74_ISO 8
  FP3_74_ISO 9
  FP3_74_ISO 10
  FP3_74_ISO 11
  FP3_74_ISO 12
  FP3_74_ISO 13
  FP3_74_ISO 14
  FP3_74_ISO 15
  FP3_75_ISO 0
  FP3_75_ISO 1
  FP3_75_ISO 2
  FP3_75_ISO 3
  FP3_75_ISO 4
  FP3_75_ISO 5
  FP3_75_ISO 6
  FP3_75_ISO 7
  FP3_75_ISO 8
  FP3_75_ISO 9
  FP3_75_ISO 10
  FP3_75_ISO 11
  FP3_75_ISO 12
  FP3_75_ISO 13
  FP3_75_ISO 14
  FP3_75_ISO 15
  FP3_76_ISO 0
  FP3_76_ISO 1
  FP3_76_ISO 2
  FP3_76_ISO 3
  FP3_76_ISO 4
  FP3_76_ISO 5
  FP3_76_ISO 6
  FP3_76_ISO 7
  FP3_76_ISO 8
  FP3_76_ISO 9
  FP3_76_ISO 10
  FP3_76_ISO 11
  FP3_76_ISO 12
  FP3_76_ISO 13
  FP3_76_ISO 14
  FP3_76_ISO 15
  FP3_77_ISO 0
  FP3_77_ISO 1
  FP3_77_ISO 2
  FP3_77_ISO 3
  FP3_77_ISO 4
  FP3_77_ISO 5
  FP3_77_ISO 6
  FP3_77_ISO 7
  FP3_77_ISO 8
  FP3_77_ISO 9
  FP3_77_ISO 10
  FP3_77_ISO 11
  FP3_77_ISO 12
  FP3_77_ISO 13
  FP3_77_ISO 14
  FP3_77_ISO 15
  FP3_78_ISO 0
  FP3_78_ISO 1
  FP3_78_ISO 2
  FP3_78_ISO 3
  FP3_78_ISO 4
  FP3_78_ISO 5
  FP3_78_ISO 6
  FP3_78_ISO 7
  FP3_78_ISO 8
  FP3_78_ISO 9
  FP3_78_ISO 10
  FP3_78_ISO 11
  FP3_78_ISO 12
  FP3_78_ISO 13
  FP3_78_ISO 14
  FP3_78_ISO 15
  FP3_79_ISO 0
  FP3_79_ISO 1
  FP3_79_ISO 2
  FP3_79_ISO 3
  FP3_79_ISO 4
  FP3_79_ISO 5
  FP3_79_ISO 6
  FP3_79_ISO 7
  FP3_79_ISO 8
  FP3_79_ISO 9
  FP3_79_ISO 10
  FP3_79_ISO 11
  FP3_79_ISO 12
  FP3_79_ISO 13
  FP3_79_ISO 14
  FP3_79_ISO 15
  FP3_80_ISO 0
  FP3_80_ISO 1
  FP3_80_ISO 2
  FP3_80_ISO 3
  FP3_80_ISO 4
  FP3_80_ISO 5
  FP3_80_ISO 6
  FP3_80_ISO 7
  FP3_80_ISO 8
  FP3_80_ISO 9
  FP3_80_ISO 10
  FP3_80_ISO 11
  FP3_80_ISO 12
  FP3_80_ISO 13
  FP3_80_ISO 14
  FP3_80_ISO 15
  FP3_81_ISO 0
  FP3_81_ISO 1
  FP3_81_ISO 2
  FP3_81_ISO 3
  FP3_81_ISO 4
  FP3_81_ISO 5
  FP3_81_ISO 6
  FP3_81_ISO 7
  FP3_81_ISO 8
  FP3_81_ISO 9
  FP3_81_ISO 10
  FP3_81_ISO 11
  FP3_81_ISO 12
  FP3_81_ISO 13
  FP3_81_ISO 14
  FP3_81_ISO 15
  Без основной надписи.
Dimensions and other numbers on the sheet: 2 этаж.; 249; 251; 252; 247; 250; 248а; 248б; 248в; 244; 246; 1; 2; 3; 4; 5; 1:1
